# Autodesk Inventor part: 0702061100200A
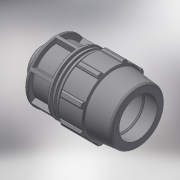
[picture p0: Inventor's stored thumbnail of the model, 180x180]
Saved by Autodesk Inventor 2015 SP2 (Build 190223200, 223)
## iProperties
Created: 2017-02
Part Number: 0702061100200A
Material: Generic
Description: PLASSON MALE ADAPTOR 110-2"
Document SubType Name: Modeling
Designer: KIM
Mass: 964.158 g
Surface Area: 1468.9 cm^2
Volume: 964.158 cm^3
Density: 1 g/cm^3
Appearance: Default
Author: KIM
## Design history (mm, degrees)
derived "87020.ipt"
feature "Solid1::87020.ipt"
tag "TaggingFeature1"
body "Solid1"
other parameters: "d4" = 37.28571, "d5" = 65.25, "d7" = 181, "d8" = 135.75, "d9" = 37.28571, "d11" = 7.45714, "d12" = 144.8, "d13" = 120 deg, "d14" = 143, "d15" = 6 deg, "d16" = 162.9, "d18" = 5.5, "d19" = 35 deg, "d20" = 17.5 deg, "d21" = 168.33, "d23" = 0, "d25" = 360 deg, "d27" = 3.62, "d34" = 9.05, "d36" = 0, "d42" = 83.52, "d43" = 5.43, "d46" = 3.3, "d49" = 213, "d51" = 261, "d52" = 26, "d53" = 2.2, "d55" = 360 deg, "d57" = 59.614, "d58" = 41.7298, "d59" = 52.2, "d61" = 159.642, "d62" = 3.82314, "d63" = 3.82314, "d66" = 7.64629, "E_" = 181, "H_" = 261, "l_" = 213, "l_2" = 26, "R_" = 59.614, "d60" = 19.11571
